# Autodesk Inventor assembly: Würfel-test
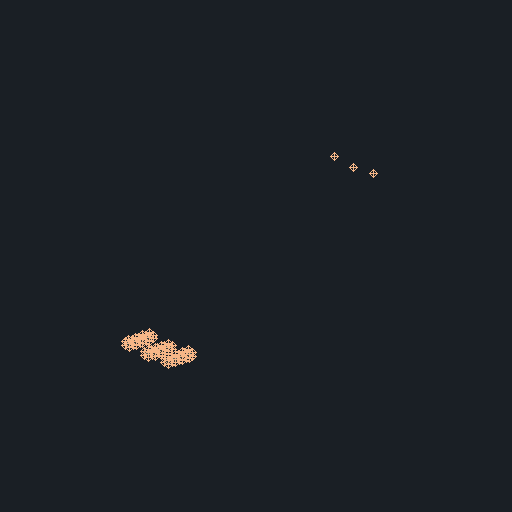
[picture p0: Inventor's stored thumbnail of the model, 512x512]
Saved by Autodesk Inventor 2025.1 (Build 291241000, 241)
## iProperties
Company: Ed. Züblin AG
Created: 2021-07
Part Number: Würfel-test
Material: Stahlbeton C30/37
Document SubType Name: Assembly
Designer: Eimannsmir
Mass: 44.4783 g
Surface Area: 94.0482 cm^2
Volume: 17.7913 cm^3
Density: 2.5 g/cm^3
z_Bereich: Tunnelbau
z_Direktion: Tief- und Tunnelbau
z_Konzerneinheit: Zentrale Technik
cpiComponentType: Attribut
cpiFitMatchkey: =<z_Matchkey>
z_Matchkey: =<z_Matchkey_010>_<z_Matchkey_020>_<z_Matchkey_030>_<z_Matchkey_040>_<z_Matchkey_050>_<z_Matchkey_060>_<z_Matchkey_070>_<z_Matchkey_080>_<z_Matchkey_090>_<z_Mat
z_Matchkey_010: xxxxx
z_Matchkey_020: 5DTUB
z_Matchkey_030: xxx
z_Matchkey_040: xxx
z_Matchkey_050: xxx
z_Matchkey_060: xxx
z_Matchkey_070: xxx
z_Matchkey_080: xxx
z_Matchkey_090: xxx
z_Matchkey_100: xxx
z_Matchkey_110: xxx
z_Matchkey_120: xxxxxxx
z_Matchkey_130: xxxx
z_Matchkey_140: xxxx
DocNumber: Würfel-test.iam
Folder: Übung\
VDS_Category: Konstruktion
Koordinate x - Ursprung: 10.0
Koordinate y - Ursprung: 0.0
Koordinate z - Ursprung: 0.0
Rotation - z-Achse: 0.0
Betondeckung: ND
Betonstahlguete: ND
Bewehrungsgehalt: ND
Druckfestigkeitsklasse: ND
Expositionsklasse_X: ND
Expositionsklasse_XA: ND
Expositionsklasse_XC: ND
Expositionsklasse_XD: ND
Expositionsklasse_XF: ND
Expositionsklasse_XM: ND
Expositionsklasse_XS: ND
Feuchtigkeitsklasse: ND
Groesstkorn: ND
Herstellungsort: ND
Luftporenbeton: ND
Rohdichte: ND
Sichtbetonklasse: ND
Unbewehrter_Beton: ND
Wasserzementwert_max: ND
WU_Beton: ND
Zusatzmittel: ND
010_Eigentuemer: ND
020_Autor: ND
030_Projektnummer: ND
040_Bereich: ND
050_Vertragspartner: ND
060_Gewerk: ND
070_Bauwerk: ND
080_Bauwerksnummer: ND
090_Bezeichnung: ND
100_Gruppe: ND
110_Element: ND
120_Elementtyp: ND
130_Identifikationsnummer: ND
140_Position_1: ND
150_Position_2: ND
160_PUID: ND
170_Hauptmaterialitaet: ND
171_Materialindikator_1: ND
172_Materialindikator_2: ND
Dicke: ND
Flaeche: ND
Streckenachse: ND
Streckenkilometer_Anfang: ND
Streckenkilometer_Ende: ND
Tunnelachse: ND
Tunnelmeter_Anfang: ND
Tunnelmeter_Ende: ND
4D_Vorgangs_ID: ND
Bauphase_Abgebrochen: ND
Bauphase_Erstellt: ND
Status: ND
Author: Eimannsmir
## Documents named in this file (2)
- C:\z_Vault\CAD\Übung\Würfel-test.iam
- C:\z_Vault\CAD\Übung\Würfel-1.iam
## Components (3 placed, 1 different names)
1. Würfel-1:1 [sub-assembly]
2. Würfel-1:2 [sub-assembly]
3. Würfel-1:3 [sub-assembly]
